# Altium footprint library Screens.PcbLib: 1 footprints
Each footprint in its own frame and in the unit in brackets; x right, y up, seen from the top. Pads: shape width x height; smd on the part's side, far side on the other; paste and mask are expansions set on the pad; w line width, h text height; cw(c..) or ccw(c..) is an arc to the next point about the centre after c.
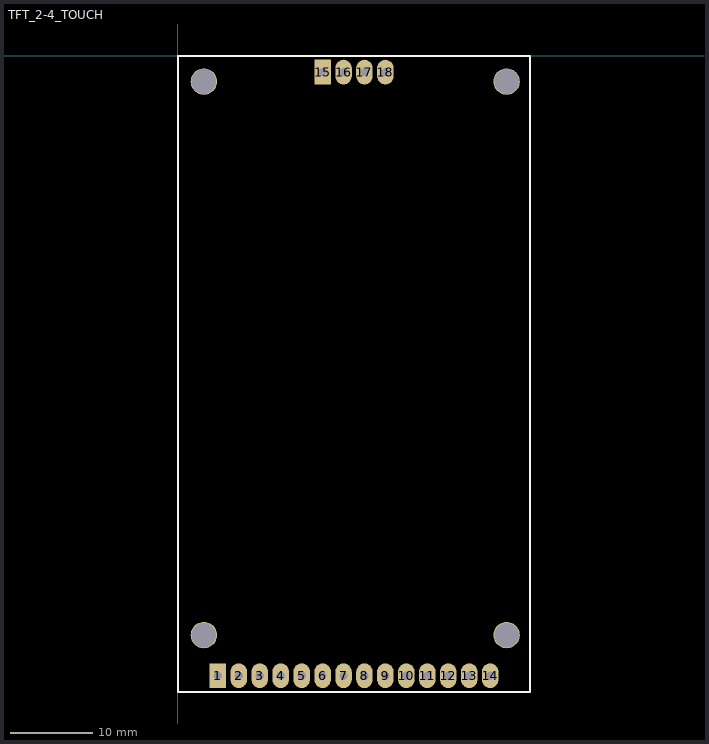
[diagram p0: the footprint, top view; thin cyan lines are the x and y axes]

## TFT_2-4_TOUCH [mm]
pads (22):
  rect 2x3 hole 1: 1(4.85,-75.208) 15(17.55,-2)
  oval 2x3 hole 1: 2(7.39,-75.208) 3(9.93,-75.208) 4(12.47,-75.208) 5(15.01,-75.208) 6(17.55,-75.208) 7(20.09,-75.208) 8(22.63,-75.208) 9(25.17,-75.208) 10(27.71,-75.208) 11(30.25,-75.208) 12(32.79,-75.208) 13(35.33,-75.208) 14(37.87,-75.208) 16(20.09,-2) 17(22.63,-2) 18(25.17,-2)
  round 3.2 hole 3: ""(3.15,-70.288) ""(3.15,-3.15) ""(39.87,-70.288) ""(39.87,-3.15)
Top Overlay:
  lines w0.254: 0,-77.208 0,-0.028 42.72,-0.028 42.72,-77.208 0,-77.208
3D body "User Library-TFT Display 2,4inch.STEP": height 14.2, standoff 0.2, extent -0.113,-77.495 42.887,0.505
